(* Logix 5000 project; controller TritexII_Demo vendor 1 type 14 code 155 rev 32.11; software revision 32.02 *)

TASK MainTask (continuous, watchdog 500 ms) : MainProgram

MODULES
   Local : vendor 1 type 14 code 155 (PointIO 0, rev 32.11)
      Tritex : ETHERNET-MODULE (Ethernet 192.168.0.254, rev 1.1, Output RPI 80 ms)
           Tritex:C   // Tritex Module - Control
           Tritex:I   // Tritex Module - Input
           Tritex:O.Data[10]   // Control Host Acceleration (high)
           Tritex:O.Data[12]   // Control input Events Move Edge
           Tritex:O.Data[2]   // Control input Events Move level
           Tritex:O.Data[11]   // Control Host Current
           Tritex:O.Data[1]   // Control input events mode
           Tritex:O.Data[3]   // Control input Events Motion
           Tritex:O.Data[4]   // Control Host Command Mode
           Tritex:O.Data[5]   // Control Host Position (low)
           Tritex:O.Data[6]   // Control Host Position (high)
           Tritex:O.Data[7]   // Control Host Velocity (low)
           Tritex:O.Data[8]   // Control Host Velocity (high)
           Tritex:O.Data[9]   // Control Host Acceleration (low)
           Tritex:O   // Tritex Module - Output
      Discrete_IO : Embedded (PointIO 1, rev 32.11, Output RPI 20 ms)
           Local:1:C   // Module - Control
           Local:1:I.Data.1   // Enable Maintained
           Local:1:I.Data.2   // Home
           Local:1:I.Data.4   // Jog+
           Local:1:I.Data.5   // Jog-
           Local:1:I   // Module - Input
           Local:1:O   // Module - Output
END_MODULES

TYPE Exlar_Control :   // Tritex II Control
STRUCT
   EnableOutputs : INT;   // EnableOutputs
   InputEventsMode : INT;   // 4316
   InputEventsModeLevel : INT;   // 4318
   InputEventsMotion : INT;   // 4317
   HostCommandControlMode : INT;   // 4303
   HostPosition_low : INT;   // 4304
   HostPosition_high : INT;
   HostVelocity_low : INT;   // 4306
   HostVelocity_high : INT;
   HostAcceleration_low : INT;   // 4308
   HostAcceleration_high : INT;
   HostCurrent : INT;   // 4310
   InputEventsMoveEdge : INT;   // 4319
   JogSlowVelocity_low : INT;   // 6022
   JogSlowVelocity_high : INT;
   JogAcceleration_low : INT;   // 6026
   JogAcceleration_high : INT;
   MoveOption : INT;   // 6100
   MoveCurrentLimit : INT;   // 6101
   MoveAcceleration_low : INT;   // 6102
   MoveAcceleration_high : INT;
   MoveDeceleration_low : INT;   // 6500
   MoveDeceleration_high : INT;
   MovePrimaryOption : INT;   // 6106
   spare : INT;   // spare
   MovePrimaryPosition_low : INT;   // 6108
   MovePrimaryPosition_high : INT;
   MovePrimaryVelocity_low : INT;   // 6110
   MovePrimaryVelocity_high : INT;
   MoveSecondaryOption : INT;   // 6112
   spare2 : INT;   // spare
   MoveSecondaryPosition_low : INT;   // 6114
   MoveSecondaryPosition_high : INT;
   MoveSecondaryVelocity_low : INT;   // 6116
   MoveSecondaryVelocity_high : INT;
END_STRUCT
END_TYPE

TYPE Exlar_Drive :   // Tritex II Data
STRUCT
   Control : Exlar_Control;   // Control bits to send to the drive
   Status : Exlar_Status;   // Status bits received from the drive
END_STRUCT
END_TYPE

TYPE Exlar_Status :   // Tritex II Status
STRUCT
   EIP_Comm : INT;   // EIP module communication
   OutputEventsStatus : INT;   // 104
   OutputEventsMoveInPosition : INT;   // 108
   OutputEventsMotion : INT;   // 105
   OutputsEventsMotionActive : INT;   // 107
   PositionFeedback_low : INT;   // 378
   PositionFeedback_high : INT;
   SoftFaults : INT;   // 7
   HardFaults : INT;   // 6
   VelocityDisplay_low : INT;   // 356
   VelocityDisplay_high : INT;
   CurrentDisplay : INT;   // 567
   CurrentContinuous : INT;   // 565
   CurrentLimit : INT;   // 5108
   VoltageHallBattery : INT;   // 8
   VoltageBus : INT;   // 571
   TemperatureBoard : INT;   // 11
   TemperatureActuator : INT;   // 15
END_STRUCT
END_TYPE

ADD_ON_INSTRUCTION T2CON   (* revision 1.0, vendor Exlar Corporation *)
// Help:
// Use the Tritex 2 Control (T2CON) instruction to send commands to drive.
// Module commands includes enabling the drive, defining Home and Motion commands like Stop and Pause.
// Configured for Exlar EIP AOI. 07/01/2014
// ----------------------------------------------------------------------------------------------------------------------------
// Parameters Bit Definition
// ----------------------------------------------------------------------------------------------------------------------------
// Module:  (Input) Tritex 2 Module Commands
// ------------------------------------------------------------------
//      Module.0:     Enable Momentary
//      Module.1:     Enable Maintained
//      Module.2:     Define Home
//      Module.3:     Brake Override
//      Module.4:     Fault Reset
// Motion:  (Input) Tritex 2 Motion Commands
// ------------------------------------------------------------------
//      Motion.0:     Stop Motion
//      Motion.1:     Pause Move
//      Motion.2:     Initiate Home Move
//      Motion.3:     Emergency Move
VAR_IN_OUT
   Drive : Exlar_Drive; {required}   // Drive
END_VAR
VAR_INPUT
   Module : INT; {visible}   // Module Commands
        .0   // Enable Momentary
        .3   // Brake Override
        .1   // Enable Maintained
        .2   // Define Home
        .4   // Fault Reset
   Motion : INT; {visible}   // Motion Commands
        .2   // Initiate Home Move
        .1   // Pause Move
        .3   // Emergency Move
        .0   // Stop Motion
END_VAR
VAR_OUTPUT
   DF : BOOL; {access Read Only, visible}   // Indicates one or more Drive Faults are Active
END_VAR

ROUTINE Logic   (* structured text *)
   (***********************************************)
   (*   Exlar Tritex 2 Control                    *)
   (*                                             *)
   (***********************************************)
   
   (********** Inputs ***********)
   
   (* Module Register *)
   	(* 4316.0 Enable Momentary *)
   	if Module.0	then
   		Drive.Control.InputEventsMode.0	:= 1;
   	else
   		Drive.Control.InputEventsMode.0 := 0;
   	end_if;
   
   	(* 4316.1 Enable Maintained *)
   	if Module.1	then
   		Drive.Control.InputEventsMode.1	:= 1;
   	else
   		Drive.Control.InputEventsMode.1	 := 0;
   	end_if;
   
   	(* 4316.10 Define Home *)
   	if Module.2	then
   		Drive.Control.InputEventsMode.10 := 1;
   	else
   		Drive.Control.InputEventsMode.10 := 0;
   	end_if;
   
   	(* 4316.14 Brake Override *)
   	if Module.3	then
   		Drive.Control.InputEventsMode.14 := 1;
   	else
   		Drive.Control.InputEventsMode.14 := 0;
   	end_if;
   
   	(* 4316.15 Fault Reset *)
   	if Module.4	then
   		Drive.Control.InputEventsMode.15 := 1;
   	else
   		Drive.Control.InputEventsMode.15 := 0;
   	end_if;
   
   (* Motion Register *)
   	(* 4317.2 Stop Motion *)
   	if Motion.0	then
   		Drive.Control.InputEventsMotion.2 := 1;
   	else
   		Drive.Control.InputEventsMotion.2  := 0;
   	end_if;
   
   	(* 4317.3 Pause Move *)
   	if Motion.1	then
   		Drive.Control.InputEventsMotion.3 := 1;
   	else
   		Drive.Control.InputEventsMotion.3 := 0;
   	end_if;
   
   	(* 4317.8 Initiate Home Move *)
   	if Motion.2	then
   		Drive.Control.InputEventsMotion.8:= 1;
   	else
   		Drive.Control.InputEventsMotion.8 := 0;
   	end_if;
   
   	(* 4317.10 Dedicated Position EMove *)
   	if Motion.3	then
   		Drive.Control.InputEventsMotion.10 := 1;
   	else
   		Drive.Control.InputEventsMotion.10  := 0;
   	end_if;
   
   (*********** OUTPUTS  ***********)
   
   (* Drive Faults Active *)
   	If Drive.Control.InputEventsMode.3 then
    		DF := 1;
   	Else
   		DF := 0;
   	End_If;
   
END_ROUTINE
END_ADD_ON_INSTRUCTION

ADD_ON_INSTRUCTION T2DRIVE   (* revision 1.0 *)
// Drive Communication
VAR_IN_OUT
   Drive_Input : INT[101]; {required}
   Drive_Output : INT[101]; {required}
   Drive : Exlar_Drive; {required}
END_VAR
VAR_OUTPUT
   ER : BOOL; {access Read Only, visible}   // Fault
   Status : DINT; {access Read Only, visible}   // EIP interface Status
END_VAR
VAR_INPUT
   OutputEnable : BOOL; {access Read Only, visible}
END_VAR

ROUTINE Logic   (* structured text *)
   (***********************************************)
   (*   Exlar Tritex 2 Drive                      *)
   (*                                             *)
   (***********************************************)
   
   	(* Enable EtherNet/IP communication board *)
   	if OutputEnable then
   		Drive.Control.EnableOutputs.0 := 1;
   	else
   		Drive.Control.EnableOutputs.0 := 0;
   	end_if;
   
   
   	(* Note: If Tritex II translation tables length are changed,
   	   CPS data size and data Type needs to change *)
   
   	(* Copy Implicit Input data to PLC Internal register - Default 18 words*)
   	cps(Drive_Input[0],Drive.Status,18);
   
   
   	(* Copy Internal registers to PLC Implicit Output - Default 36 words *)
   	cps(Drive.Control, Drive_Output[0],36);
   
   
   	(* Tritex communication status *)
   	if 	Drive.Status.EIP_Comm.0 or
   		Drive.Status.EIP_Comm.1 or
   		Drive.Status.EIP_Comm.2 then
   		ER := 1;
   	else
   		ER := 0;
   	end_if;
   
   
   	(* Copy  Communication Status registers *)
   		Status := Drive.Status.EIP_Comm;
   		Status := Status AND 16#0000FFFF;
   
   	 (* StatusRegister
   		  	Bit				Description
   			=======			===============================
   			.0				Error - Tritex responded with error code
   							Read Extended Module Status(Object 64h,Instance 1,Attribute 101) for Modbus error
   			.1				Error - Communication between EIP module and Tritex timed-out
   			.2				Error - Communication between EIP module and Tritex cannot be established
   			.3-7			Reserved
   			.8				EIP interface is currently active at factory defaults
   			.9				EIP interface has a new configuration
   			.10-15			Reserved
   	 *)
END_ROUTINE
END_ADD_ON_INSTRUCTION

ADD_ON_INSTRUCTION T2HC   (* revision 1.1, vendor Exlar Corporation *)
// Help:
// Use the Tritex 2 HC(T2HC) instruction to control drive Host Control Option
// Configured for Exlar EIP AOI. 07/01/2014
// ----------------------------------------------------------------------------------------------------------------------------
// Parameters Bit Definition
// ----------------------------------------------------------------------------------------------------------------------------
// CommandMode:   (Input) Control Host Mode
// ------------------------------------------------------------------
//    0 = Disable Host Control
//    5 = Position
//    6 = Velocity
//    7 = Current
VAR_IN_OUT
   Drive : Exlar_Drive; {required}   // Drive
   Units : REAL[5]; {required}   // Units
END_VAR
VAR_INPUT
   CommandMode : INT; {visible}   // Host Control
   Position : REAL; {visible}   // Position
   Velocity : REAL; {visible}   // Velocity
   Acceleration : INT; {visible}   // Acceleration
   Current : REAL; {visible}   // Current
END_VAR
VAR_OUTPUT
   DF : BOOL; {access Read Only, visible}   // A Drive Fault is active
   ER : BOOL; {access Read Only, visible}   // A Instruction error is Active
END_VAR
VAR
   tempDINT : DINT; {access None}   // Temporary Register used in calculating units
END_VAR

ROUTINE Logic   (* structured text *)
   (***********************************************)
   (*   Exlar Tritex 2 Host Control               *)
   (*                                             *)
   (***********************************************)
   
   
   (* Precondition  *)
   	ER	:= 0;
   
   (* Check valid Host Control *)
   	(* CommandMode
   		 0 = Disabled
            5 = Position
            6 = Velocity
            7 = Current
   	*)
   	if CommandMode = 0 OR CommandMode = 5
   		OR CommandMode = 6 OR CommandMode = 7 then
   
   		(* ID:4303, Control.Host.CommandMode:  Outputs[4]] *)
   		Drive.Control.HostCommandControlMode := CommandMode;
   	else
   		ER	:= 1;
   		Drive.Control.HostCommandControlMode := 0;
   	end_if;
   
   
   (********** Outputs **********)
   (* Drive Faults Active *)
   	(* 104.03 Fault *)
   	if Drive.Status.OutputEventsStatus.3 then
    		DF := 1;
   	Else
   		DF := 0;
   	End_If;
   
   
   (* Error Test *)
   	(* User Units Instruction error active ? *)
   	IF Units[0] = 0 THEN
   		ER	:= 1;
   	end_if;
   
   (* Update Units *)
   	if NOT ER  then
   
   		(* Position *)
   		(* ID:4304, Control.Host.Postion:  ModuleOutputs[6],ModuleOutputs[5] *)
   		tempDINT := Position / Units[1];
   		cps(tempDINT, Drive.Control.HostPosition_low,2);
   
   		(* Velocity *)
   		(* ID:4306, Control.Host.Velocity:  ModuleOutputs[8],ModuleOutputs[7] *)
   		tempDINT := Velocity / Units[2];
   		cps(tempDINT, Drive.Control.HostVelocity_low,2);
   
   		(* Acceleration *)
   		(* ID:4308, Control.Host.Acceleration:  ModuleOutputs[10],ModuleOutputs[9] *)
   		tempDINT := Acceleration / Units[3];
   		cps(tempDINT, Drive.Control.HostAcceleration_low,2);
   
   		(* Current Scale   *)
   		(*       0: AMPs   *)
   		(*       1: %      *)
   		(* ID:4310, Control.Host.Current:  ModuleOutputs[11] *)
   		if Units[4] = 0	then
   			Drive.Control.HostCurrent := Current / 0.0078125 ;
   		else
   			(* Use for % ,ID:5108, Config.CurrentLimit:   ModuleInputs[13],  *)
   			Drive.Control.HostCurrent := Drive.Status.CurrentLimit * (Current /100);
   		end_if;
   
   	end_if;
   
   
   
END_ROUTINE
END_ADD_ON_INSTRUCTION

ADD_ON_INSTRUCTION T2JOG   (* revision 1.1, vendor Exlar Corporation *)
// Help:
// Use the Tritex 2 Jog (T2JOG) instruction to move an a drive at a constant speed until you tell it to stop.
// Jog commands includes enabling Jog Positive or Negative.  The instruction allow user to select profile velocity and acceleration in user units.
// Configured for Exlar EIP AOI. 07/01/2014
// ----------------------------------------------------------------------------------------------------------------------------
// Parameters Bit Definition
// ----------------------------------------------------------------------------------------------------------------------------
// Direction:  (Input) Command Jog Direction
// ------------------------------------------------------------------
//      Direction.0:     Jog Plus
//      Direction.1:     Jog Minus
// Active:  (Output) Jog status information
// ------------------------------------------------------------------
//      Active.0:     Jog Plus active
//      Active.1:     Jog Minus active
//      Active.2:     Ready
VAR_IN_OUT
   Drive : Exlar_Drive; {required}   // Drive
   Units : REAL[5]; {required}   // User Units Configuration
END_VAR
VAR_INPUT
   Direction : INT; {access Read Only, visible}   // Jog Control
        .0   // JOGP
        .1   // JOGN
   Velocity : REAL; {access Read Only, visible}   // Speed to move the drive in Speed Units.
   Acceleration : REAL; {access Read Only, visible}   // Acceleration rate of the drive in Accel Units.
END_VAR
VAR_OUTPUT
   DF : BOOL; {access Read Only, visible}   // A Drive Fault is active
   ER : BOOL; {access Read Only, visible}   // A Instruction error is Active
   Active : INT; {access Read Only, visible}   // Jog Active States
        .0   // JOGP
        .3   // READY
        .1   // JOGN
        .2   // STOPPED
END_VAR
VAR
   tempDINT : DINT; {access None}   // Temporary Register used in calculating units
END_VAR

ROUTINE Logic   (* structured text *)
   (***********************************************)
   (*   Exlar Tritex 2 Jog                        *)
   (*                                             *)
   (***********************************************)
   
   
   
   (*********** INPUTS ***********)
   
   (* Direction *)
   	(* 4317.4 Jog Positive *)
   	If Direction.0 Then
   		Drive.Control.InputEventsMotion.4 := 1;
   	else
   		Drive.Control.InputEventsMotion.4 := 0;
   	end_if;
   
   	(* 4317.5 Jog Minus *)
   	If Direction.1 Then
   		Drive.Control.InputEventsMotion.5 := 1;
   	else
   		Drive.Control.InputEventsMotion.5 := 0;
   	end_if;
   
   (*********** OUTPUTS  ***********)
   
   (* Drive Faults Active *)
   	(* 104.03 Fault *)
   	If Drive.Status.OutputEventsStatus.3 then
    		DF := 1;
   	Else
   		DF := 0;
   	End_If;
   
   (* Active States  *)
   	(* 105.3 JOG Positive *)
   	If Drive.Status.OutputEventsMotion.3 Then
   		Active.0 := 1;
   	else
   		Active.0 := 0;
   	end_if;
   
   	(* 105.4 JOG Minus *)
   	If Drive.Status.OutputEventsMotion.4 Then
   		Active.1 := 1;
   	else
   		Active.1 := 0;
   	end_if;
   
   
   	(* 105.0 STOPPED *)
   	If Drive.Status.OutputEventsMotion.0 Then
   		Active.2 := 1;
   	else
   		Active.2 := 0;
   	end_if;
   
   	(* 104.2 Ready *)
   	If Drive.Status.OutputEventsStatus.2 Then
   		Active.3 := 1;
   	else
   		Active.3 := 0;
   	end_if;
   
   
   (* Convert Units *)
   	IF Units[0] = 0 THEN
   		ER	:= 1;
   	else
   		ER  := 0;
   
   		(* Jog.SlowVelovity : ModuleOutputs[14],ModuleOutputs[13] *)
   		tempDINT := Velocity / Units[2];
   		cps(tempDINT, Drive.Control.JogSlowVelocity_low,2);
   
   		(* Jog.Acceleration: ModuleOutputs[16],ModuleOutputs[15] *)
   		tempDINT := Acceleration / Units[3];
   		cps(tempDINT, Drive.Control.JogAcceleration_low,2);
   
   	end_if;
END_ROUTINE
END_ADD_ON_INSTRUCTION

ADD_ON_INSTRUCTION T2MOV   (* revision 1.1, vendor Exlar Corporation *)
// Help:
// Use the Tritex 2 Move (T2MOV) instruction to execute an drive move command
// The Move instruction is used to set up move profile parameters for both primary and secondary move.  The AOI also includes the ability to control the execution of the move.
// Configured for Exlar EIP AOI. 07/01/2014
// ----------------------------------------------------------------------------------------------------------------------------
// Parameters Bit Definition
// ----------------------------------------------------------------------------------------------------------------------------
// Execute:   (Input) Control Move 0 commands
// ------------------------------------------------------------------
//      Execute.0:     Move 0 Maintained
//      Execute.1:     Move 0 Momentary
// Options:   (Input) Move 0 Options
// ------------------------------------------------------------------
//      Options.0:     Secondary Motion Enable
// PrimOption:   (Input) Move 0 Primary Options
// ------------------------------------------------------------------
//      PrimOption.2.1.0:    Three bits determine Primary Move Options
//                                     %000 = Absolute Position
//                                     %001 = Incremental
//                                     %010 = Unlimited(+)
//                                     %011 = Unlimted(-)
//                                     %100 = Absolute(+) only
//                                     %101 = Absolute(-) only
//      PrimOption.3:     Limit maximum Current
//      PrimOption.4:     Terminate on Current Limit
//      PrimOption.5:     Fault if terminated by current limit
// SecOption:   (Input) Move 0 Secondary Options
// ------------------------------------------------------------------
//      SecOption.2.1.0:    Three bits determine Secondary Move Options
//                                     %000 = Absolute Position
//                                     %001 = Incremental
//                                     %010 = Unlimited(+)
//                                     %011 = Unlimted(-)
//                                     %100 = Absolute(+) only
//                                     %101 = Absolute(-) only
//      SecOption.3:     Limit maximum Current
//      SecOption.4:     Terminate on Current Limit
//      SecOption.5:     Fault if terminated by current limit
// Active:  (Output) Move 0 status information
// ------------------------------------------------------------------
//      Active.0:     Ready -  is set when both the ENABLED and HOMED flags are active.
//      Active.1:     Move 0 in Position
//      Active.2:     Move 0 active
VAR_IN_OUT
   Drive : Exlar_Drive; {required}   // Drive
   Units : REAL[5]; {required}   // Units
END_VAR
VAR_INPUT
   Execute : INT; {visible}   // Move Control
        .1   // Momentary
        .0   // Maintained
   Options : INT; {visible}   // Move Options
        .0   // Secondary Motion Enable
   CurrentLimit : REAL; {visible}   // Move Current Limit
   Acceleration : INT; {visible}   // Acceleration rate of the drive in Accel Units
   Deceleration : INT; {visible}   // Deceleration rate of the drive in Accel Units
   Prim_Position : REAL; {visible}   // Absolute position or incremental distance for the move
   Prim_Velocity : REAL; {visible}   // Speed to move the drive in Speed Units
   Prim_Option : INT; {visible}   // Primary Move Options
        .3   // Limit maximum Current
        .4   // Terminate on Current Limit
        .5   // Fault if terminated by current limit
        .0   // TYPE Bit
        .1   // TYPE Bit
        .2   // TYPE Bit
   Sec_Position : REAL; {visible}   // Absolute position or incremental distance for the move
   Sec_Velocity : REAL; {visible}   // Speed to move the drive in Speed Units
   Sec_Option : INT; {visible}   // Secondary Move Options
        .3   // Limit maximum Current
        .4   // Terminate on Current Limit
        .5   // Fault if terminated by current limit
        .0   // TYPE Bit
        .1   // TYPE Bit
        .2   // TYPE Bit
END_VAR
VAR_OUTPUT
   DF : BOOL; {access Read Only, visible}   // A Drive Fault is active
   ER : BOOL; {access Read Only, visible}   // A Instruction error is Active
   IP : BOOL; {access Read Only, visible}   // Move 0 In Position
   Active : INT; {access Read Only, visible}   // Active
        .1   // Move 0 In Position
        .2   // Move 0 active
        .0   // Ready
END_VAR
VAR
   tempDINT : DINT; {access None}   // Temporary Register used in calculating units
END_VAR

ROUTINE Logic   (* structured text *)
   (***********************************************)
   (*   Exlar Tritex 2 Move                       *)
   (*                                             *)
   (***********************************************)
   (*
    Revision History
    -------
    3.7.2023   Fixed bug of array pointer for Modbus ID 6101 scaling
   
   *)
   
   (********** Inputs ***********)
   
   (* Execute *)
   	(* 4318.0  Move 0 Maintained *)
   	if Execute.0 then
   		Drive.Control.InputEventsModeLevel.0 := 1;
   	else
   		Drive.Control.InputEventsModeLevel.0 := 0;
   	end_if;
   
   	(* 4319.0  Move 0 Momentary *)
   	if Execute.1 then
   		Drive.Control.InputEventsMoveEdge.0 := 1;
   	else
   		Drive.Control.InputEventsMoveEdge.0 := 0;
   	end_if;
   
   (* Option *)
   	(* 6100.0  Secondary Motion Enable *)
   	if Options.0 then
   		Drive.Control.MoveOption.0 := 1;
   	else
   		Drive.Control.MoveOption.0 := 0;
   	end_if;
   
   (* Primary Option *)
   	(* 6106.0  - Move Type *)
   	if Prim_Option.0 then
   		Drive.Control.MovePrimaryOption.0 := 1;
   	else
   		Drive.Control.MovePrimaryOption.0 := 0;
   	end_if;
   	(* 6106.1  - Move Type *)
   	if Prim_Option.1 then
   		Drive.Control.MovePrimaryOption.1 := 1;
   	else
   		Drive.Control.MovePrimaryOption.1 := 0;
   	end_if;
   	(* 6106.2  - Move Type *)
   	if Prim_Option.2 then
   		Drive.Control.MovePrimaryOption.2 := 1;
   	else
   		Drive.Control.MovePrimaryOption.2 := 0;
   	end_if;
   
   	(* 6106.4 Limit maximum Current *)
   	if Prim_Option.3 then
   		Drive.Control.MovePrimaryOption.4 := 1;
   	else
   		Drive.Control.MovePrimaryOption.4 := 0;
   	end_if;
   
   	(* 6106.8 Terminate on Current Limit *)
   	if Prim_Option.4 then
   		Drive.Control.MovePrimaryOption.8 := 1;
   	else
   		Drive.Control.MovePrimaryOption.8 := 0;
   	end_if;
   
   	(* 6106.12 Fault if terminated by current limit *)
   	if Prim_Option.5 then
   		Drive.Control.MovePrimaryOption.12 := 1;
   	else
   		Drive.Control.MovePrimaryOption.12 := 0;
   	end_if;
   
   (* Secondary Option	*)
   	(* 6112.0  - Move Type *)
   	if Sec_Option.0 then
   		Drive.Control.MoveSecondaryOption.0:= 1;
   	else
   		Drive.Control.MoveSecondaryOption.0	:= 0;
   	end_if;
   
   	(* 6112.1  - Move Type *)
   	if Sec_Option.1 then
   		Drive.Control.MoveSecondaryOption.1	 := 1;
   	else
   		Drive.Control.MoveSecondaryOption.1	 := 0;
   	end_if;
   
   	(* 6112.2  - Move Type *)
   	if Sec_Option.2 then
   		Drive.Control.MoveSecondaryOption.2	 := 1;
   	else
   		Drive.Control.MoveSecondaryOption.2	 := 0;
   	end_if;
   
   	(* 6112.4 Limit maximum Current *)
   	if Sec_Option.3 then
   		Drive.Control.MoveSecondaryOption.4	 := 1;
   	else
   		Drive.Control.MoveSecondaryOption.4	 := 0;
   	end_if;
   
   	(* 6112.8 Terminate on Current Limit *)
   	if Sec_Option.4 then
   		Drive.Control.MoveSecondaryOption.8	 := 1;
   	else
   		Drive.Control.MoveSecondaryOption.8	 := 0;
   	end_if;
   
   	(* 6112.12 Fault if terminated by current limit *)
   	if Sec_Option.5 then
   		Drive.Control.MoveSecondaryOption.12	 := 1;
   	else
   		Drive.Control.MoveSecondaryOption.12	 := 0;
   	end_if;
   
   
   (********** Outputs **********)
   (* Drive Faults Active *)
   	(* 104.03 Fault *)
   	If Drive.Status.OutputEventsStatus.3 then
    		DF := 1;
   	Else
   		DF := 0;
   	End_If;
   
   (* Active *)
   	(* 104.2 Ready *)
   	If Drive.Status.OutputEventsStatus.2 Then
   		Active.0 := 1;
   	else
   		Active.0 := 0;
   	end_if;
   
   	(* 108.0 Move 0 in Position *)
   	If Drive.Status.OutputEventsMoveInPosition.0 Then
   		Active.1 := 1;
   		IP := 1;
   	else
   		Active.1 := 0;
   		IP := 0;
   	end_if;
   
   	(* 107.0 Move 0 Moving *)
   	If Drive.Status.OutputsEventsMotionActive.0 Then
   		Active.2 := 1;
   	else
   		Active.2 := 0;
   	end_if;
   
   
   (* Convert Units *)
   	IF Units[0] = 0 THEN
   		ER	:= 1;
   	else
   		ER  := 0;
   
   		(** Move Group **)
   	 	(* ID:6102, Move.0.Acceleration:  ModuleOutputs[20],ModuleOutputs[19] *)
   		tempDINT := Acceleration / Units[3];
   		cps(tempDINT, Drive.Control.MoveAcceleration_low,2);
   
   		(* ID:6500, Move.0.Deceleration:  ModuleOutputs[22],ModuleOutputs[21] *)
   		tempDINT := Deceleration / Units[3];
   		cps(tempDINT, Drive.Control.MoveDeceleration_low,2);
   
   		(* Primary Group **)
   		(* ID:6110, Move.0.Primary.Velocity:  ModuleOutputs[28],ModuleOutputs[27] *)
   		tempDINT := Prim_Velocity / Units[2];
   		cps(tempDINT, Drive.Control.MovePrimaryVelocity_low,2);
   
   		(* Secondary Group **)
   		(* ID:6116, Move.0.Secondary.Velocity:  ModuleOutputs[34],ModuleOutputs[33] *)
   		tempDINT := Sec_Velocity / Units[2];
   		cps(tempDINT, Drive.Control.MoveSecondaryVelocity_low,2);
   
   		(* ID:6114, Move.0.Secondary.Position:  ModuleOutputs[32],ModuleOutputs[31] *)
   		tempDINT := Sec_Position / Units[1];
   		cps(tempDINT, Drive.Control.MoveSecondaryPosition_low,2);
   
   		(* ID:6108, Move.0.Primary.Position:  ModuleOutputs[26],ModuleOutputs[25] *)
   		tempDINT := Prim_Position / Units[1];
   		cps(tempDINT, Drive.Control.MovePrimaryPosition_low,2);
   
   
   		(* Current Scale   *)
   		(*       0: AMPs   *)
   		(*       1: %      *)
   		(* ID:6101,  Move.0.CurrentLimit:  ModuleOutputs[18] *)
   		if Units[4] = 0	then
   			Drive.Control.MoveCurrentLimit := CurrentLimit / 0.0078125 ;
   		else
   			(* Use for % ,ID:5108, Config.CurrentLimit:   ModuleInputs[13],  *)
   			Drive.Control.MoveCurrentLimit := Drive.Status.CurrentLimit * (CurrentLimit /100);
   		end_if;
   	end_if;
   
   
   
   
   
   
   
   
   
   
END_ROUTINE
END_ADD_ON_INSTRUCTION

ADD_ON_INSTRUCTION T2STA   (* revision 1.0, vendor Exlar Corporation *)
// Help:
// Use the Tritex 2 Status (T2STA) instruction to retrieve drive status. The instruction parameters provide a summary view of the module, motion and position information for the drive.
// Configured for Exlar EIP AOI. 07/01/2014
// ----------------------------------------------------------------------------------------------------------------------------
// Parameters Bit Definition
// ----------------------------------------------------------------------------------------------------------------------------
// Module:   (Output) Module Status
// ------------------------------------------------------------------
//      Module.0:     Enable
//      Module.1:     Homed
//      Module.2:     Ready
//      Module.3:     Fault Active
//      Module.4:     Warning Active
//      Module.5:     Fault or Warning Active
// Motion:   (Output) Motion Status
// ------------------------------------------------------------------
//      Motion.0:     Stopped Active
//      Motion.1:     Pasued Active
//      Motion.2:     Jogged Active
//      Motion.3:     Jog Positive Active
//      Motion.4:     Jog Negative Active
//      Motion.5:     Initiate Home Move Active
//      Motion.6:     Emergency Move Active
//      Motion.7:     Move Active
//      Motion.8:     In Position Active
// Warnings:     (Output) List of active drive Warnings
// ------------------------------------------------------------------
//      Warnings.0:  IPK – Peak Current
//      Warnings.1:  C – Continuous Current
//      Warnings.2:  POS – Position Tracking
//      Warnings.3:  MV – Move Termination
//      Warnings.4:  VLOW – Low DC Bus Voltage
//      Warnings.5:  VHIGH – High DC Bus Voltage
//      Warnings.6:  FE – Positional Following Error
//      Warnings.7:  BT – Board Temperature
//      Warnings.8:  AT – Actuator Temperature
//      Warnings.9:  LOS – Loss of Signal
//      Warnings.10:  COM –Communications
//      Warnings.11:  IH – Hardware Over current
//      Warnings.12:  HB – Absolute Hall Board Battery
//      Warnings 13:  UP – User Parameters
//      Warnings.14:  FP – Factory Parameters
//      Warnings.15:  RS – Restart
// Faults:     (Output)  List of active drive Faults
// ------------------------------------------------------------------
//      Faults.0:  IPK – Peak Current
//      Faults.1:  C – Continuous Current
//      Faults.2:  POS – Position Tracking
//      Faults.3:  MV – Move Termination
//      Faults.4:  VLOW – Low DC Bus Voltage
//      Faults.5:  VHIGH – High DC Bus Voltage
//      Faults.6:  FE – Positional Following Error
//      Faults.7:  BT – Board Temperature
//      Faults.8:  AT – Actuator Temperature
//      Faults.9:  LOS – Loss of Signal
//      Faults.10:  COM –Communications
//      Faults.11:  IH – Hardware Over current
//      Faults.12:  HB – Absolute Hall Board Battery
//      Faults 13:  UP – User Parameters
//      Faults.14:  FP – Factory Parameters
//      Faults.15:  RS – Restart
VAR_IN_OUT
   Drive : Exlar_Drive; {required}   // Drive
   Units : REAL[5]; {required}   // User Units Configuration
END_VAR
VAR_OUTPUT
   DF : BOOL; {access Read Only, visible}   // A Drive Fault is active
   ER : BOOL; {access Read Only, visible}   // A Instruction error is Active
   Ready : BOOL; {access Read Only, visible}   // Enabled + Homed
   Module : INT; {access Read Only, visible}   // Drive Status
        .10   // Define Home Position 1
        .11   // Define Home Position 2
        .7   // Alternate Operating Mode
        .13   // Teach Selected Move Position
        .15   // Fault Reset
        .1   // Homed
        .2   // Ready
        .12   // Move Teach Enable
        .0   // Enable
        .3   // Fault
        .4   // Warning
        .14   // Brake Override
        .5   // Fault or Warning
   Motion : INT; {access Read Only, visible}   // Motion Status
        .8   // In Position active
        .6   // EMOVE
        .3   // Jog Positive Actived
        .1   // Pasued Active
        .2   // Jogged Active
        .0   // Stopped Active
        .5   // Initiate Home Move Active
        .4   // Jog Negative Active
        .7   // Move active
   Position : REAL; {access Read Only, visible}   // Module Position
   Velocity : REAL; {access Read Only, visible}   // Module Velocity
   ContinuousCurrent : REAL; {access Read Only, visible}   // Continous Current
   ActualCurrent : REAL; {access Read Only, visible}   // Actual Current
   Battery : INT; {access Read Only, visible}   // Battery Voltage if available
   BusVoltage : INT; {access Read Only, visible}   // Bus Voltage
   BoardTemp : INT; {access Read Only, visible}   // Board Temperature
   ActuatorTemp : INT; {access Read Only, visible}   // Actuator Temperature
   Warnings : INT; {access Read Only, visible}   // Warnings
        .12   // AB- Absolute Hall Board Battery
        .1   // C - Continuous Current
        .10   // COM - Communications
        .11   // IH - Hardware Over current
        .0   // IPK- Peak Current
        .13   // UP - User Parameters
        .3   // MV - Move Termination
        .5   // VHIGH - High DC Bus Voltage
        .6   // FE - Positional Following Error
        .7   // BT - Board Temperature
        .14   // FP - Factory Parameters
        .9   // LOS - Loss of Signal
        .4   // VLOW - Low DC Bus Voltage
        .15   // RS - Restart
        .2   // POS - Position Tracking
        .8   // AT - Actuator Temperature
   Faults : INT; {access Read Only, visible}   // Faults
        .0   // IPK- Peak Current
        .1   // C - Continuous Current
        .10   // COM - Communications
        .11   // IH - Hardware Over current
        .12   // HB - Absolute Hall Board Battery
        .13   // UP - User Parameters
        .3   // MV - Move Termination
        .5   // VHIGH - High DC Bus Voltage
        .6   // FE - Positional Following Error
        .7   // BT - Board Temperature
        .14   // FP - Factory Parameters
        .9   // LOS - Loss of Signal
        .4   // VLOW - Low DC Bus Voltage
        .2   // POS - Position Tracking
        .15   // RS - Restart
        .8   // AT - Actuator Temperature
END_VAR
VAR
   tempDINT : DINT; {access None}   // Temporary Register used in calculating units
END_VAR

ROUTINE Logic   (* structured text *)
   (***********************************************)
   (*   Exlar Tritex 2 Status                     *)
   (*                                             *)
   (***********************************************)
   
   (*********** OUTPUTS  ***********)
   
   (* Drive Faults Active *)
   	(* 104.03 Fault *)
   	If Drive.Status.OutputEventsStatus.3 then
    		DF := 1;
   	Else
   		DF := 0;
   	End_If;
   
   (* Ready Active *)
   	(* 104.02 Ready *)
   	if Drive.Status.OutputEventsStatus.2 then
   		Ready := 1;
   	else
   		Ready := 0;
   	End_if;
   
   (* Drive Warnings Active *)
   (* ID:7, Status.Mode.SoftFaults : ModuleInputs[7]*)
   	Warnings := Drive.Status.SoftFaults;
   
   (* Drive Faults Active *)
   (* ID:6, Status.Mode.HardFaults : ModuleInputs[8]*)
   	Faults := Drive.Status.HardFaults;
   
   (* Module  *)
   	(* 104.00 Enable *)
   	(* 104.01 Homed *)
   	(* 104.02 Ready *)
   	(* 104.03 Fault *)
   	(* 104.04 Warning *)
   	(* 104.05 Fault or Warning *)
   	Module := Drive.Status.OutputEventsStatus AND 16#3F;
   
   (* Motion *)
   	(* 105.00 Stopped Active *)
   	If Drive.Status.OutputEventsMotion.0 Then
   		Motion.0 := 1;
   	else
   		Motion.0 := 0;
   	end_if;
   
   	(* 105.01 Pause *)
   	If Drive.Status.OutputEventsMotion.1 Then
   		Motion.1 := 1;
   	else
   		Motion.1 := 0;
   	end_if;
   
   	(* 105.02 Jogging *)
   	If Drive.Status.OutputEventsMotion.2 Then
   		Motion.2 := 1;
   	else
   		Motion.2 := 0;
   	end_if;
   
   	(* 105.03 Jogging Plus *)
   	If Drive.Status.OutputEventsMotion.3 Then
   		Motion.3 := 1;
   	else
   		Motion.3 := 0;
   	end_if;
   
   	(* 105.04 Jogging Minus *)
   	If Drive.Status.OutputEventsMotion.4 Then
   		Motion.4 := 1;
   	else
   		Motion.4 := 0;
   	end_if;
   
   	(* 105.05 Homing Active *)
   	If Drive.Status.OutputEventsMotion.5 Then
   		Motion.5 := 1;
   	else
   		Motion.5 := 0;
   	end_if;
   
   	(* 105.08 Dedicated Move Active *)
   	If Drive.Status.OutputEventsMotion.8 Then
   		Motion.6 := 1;
   	else
   		Motion.6 := 0;
   	end_if;
   
   	(* 105.09 Move Active *)
   	If Drive.Status.OutputEventsMotion.9 Then
   		Motion.7 := 1;
   	else
   		Motion.7 := 0;
   	end_if;
   
   	(* 105.12 Input Position *)
   	If Drive.Status.OutputEventsMotion.12 Then
   		Motion.8 := 1;
   	else
   		Motion.8 := 0;
   	end_if;
   
   (* Units  *)
   	IF Units[0] = 0 THEN
   		ER := 1;
   	else
   		ER := 0;
   
   		(* Velocity *)
   		(*  ID:356, Status.Velocity.Display:    ModuleInputs[10],ModuleInputs[9] *)
   		cps(Drive.Status.VelocityDisplay_low,tempDINT,2);
   		Velocity    :=  tempDINT * Units[2];
   
   		(* Position *)
   		(*	ID:378, Status.Position.Feedback:   ModuleInputs[6],ModuleInputs[5]  *)
   		cps(Drive.Status.PositionFeedback_low,tempDINT,2);
   		Position	:=	tempDINT * Units[1];
   
   		(* Current scale ? *)
   		(*       0: AMPs   *)
   		(*       1: %      *)
   		if Units[4] = 0	then
   			(* ID:567, Status.Current.Display:  ModuleInputs[11]  *)
   			ActualCurrent := Drive.Status.CurrentDisplay * 0.0078125;
   
   			(* ID:565, Status.Current.Continuous:  ModuleInputs[12]*)
   			ContinuousCurrent := Drive.Status.CurrentContinuous * 0.0078125;
   		else
   			(* Use for %,ID:5108, Config.CurrentLimit:   ModuleInputs[13],  *)
   			ActualCurrent  :=  (Drive.Status.CurrentDisplay / Drive.Status.CurrentLimit) * 100;
   			ContinuousCurrent :=  (Drive.Status.CurrentContinuous / Drive.Status.CurrentLimit) * 100;
   		end_if;
   	end_if;
   
   (*	ID:15,  Status.Temperature.Actuator:ModuleInputs[17] *)
    	ActuatorTemp 	:=	Drive.Status.TemperatureActuator * 0.125;
   (*	ID:11,  Status.Temperature.Board: 	ModuleInputs[16] *)
   	BoardTemp		:=	Drive.Status.TemperatureBoard * 0.03125;
   (*	ID:571, Status.Voltage.Vbus:    	ModuleInputs[15] *)
   	BusVoltage		:=	Drive.Status.VoltageBus *  0.03125;
   (*	ID:08,  Status.Voltage.HallBattery: ModuleInputs[14] *)
   
   
END_ROUTINE
END_ADD_ON_INSTRUCTION

ADD_ON_INSTRUCTION T2UU   (* revision 1.0, vendor Exlar Corporation *)
// Help:
// Use the Tritex 2 User Units (T2UU) instruction to calculate user units. User units are easy-to-understand units of measurement that simplify your programming tasks. You define user units via parameters DistUUPerRev, VelTimeScale and CurrentScale.
// Configured for Exlar EIP AOI. 07/01/2014
// ----------------------------------------------------------------------------------------------------------------------------
// Parameters Bit Definition
// ----------------------------------------------------------------------------------------------------------------------------
// VelTimeScale:  (Input) Select the units you want for velocity.
//                          This will also effect acceleration
// ------------------------------------------------------------------
//      VelTimeScale = 0:     Seconds  (Velocity: Units/S,  Acceleration:  Units/S/S)
//      VelTimeScale = 1:     Minutes    (Velocity: Units/M, Acceleration:  Units/S/M)
// CurrentScale:  (Input) Select the units you want for Current
// ------------------------------------------------------------------
//      CurrentScale = 0:     AMPS
//      CurrentScale = 1:     % of Current Limit (Modbus ID 5108)
VAR_INPUT
   DistScale : REAL; {visible}   // Distance User Units Per Rev
   VelScale : REAL; {visible}   // Velocity Scale
   AccScale : REAL; {visible}   // Acceleration Scale
   CurrentScaling : INT; {visible}   // Current Scale
END_VAR
VAR_IN_OUT
   Units : REAL[5]; {required}   // Units Scale Results
        [0]   // Status
        [2]   // Velocity Scale
        [3]   // Acceleration Scale
        [4]   // Current Scaling Method
        [1]   // Distance
END_VAR
VAR_OUTPUT
   ER : BOOL; {access Read Only, visible}   // A Instruction error is Active
END_VAR

ROUTINE Logic   (* structured text *)
   (***********************************************)
   (*   Exlar Tritex 2 User Units                 *)
   (*                                             *)
   (***********************************************)
   
   
   
   (* Check for Error *)
   	if ((DistScale = 0) or (VelScale = 0)or (AccScale = 0 ))then
   		ER := 1;
   		Units[0] := 0;
   	else
   		ER := 0;
   		Units[0] := 1;
   	End_if;
   
   (* Load Global Units       *)
   	(* Current Scale       *)
   	(*       0: AMPs       *)
   	(*       1: % of Rated *)
   
   	(* Distance User Units per Rev *)
   	(*Units[0] := Units Status *)
   	Units[1] := DistScale;
   	Units[2] := VelScale;
   	Units[3] := AccScale;
   	Units[4] := CurrentScaling AND 16#1;
   
   
   
END_ROUTINE
END_ADD_ON_INSTRUCTION

VAR_GLOBAL   (* controller tags *)
   CurrentFeedback : REAL := 0.0234375;   // Scale Current
   Drive_Control : T2CON;   // AOI - T2CON
   Drive_Host : T2HC := (Position := 20.0, Velocity := 500.0, Acceleration := 2000, Current := 5.0);   // AOI - T2HC
   Drive_Jog : T2JOG := (Velocity := 89.0, Acceleration := 40.0);   // AOI - T2JOG
   Drive_Move : T2MOV := (Options := 13, CurrentLimit := 45.0, Acceleration := 7, Deceleration := 7, Prim_Position := 2.0, Prim_Velocity := 5.0, Sec_Position := 4.542, Sec_Velocity := 1.5);   // AOI - T2MOV
   Drive_Status : T2STA := (Position := -1.5258789e-05, Velocity := 0.4899466, ContinuousCurrent := 0.0234375, ActualCurrent := 0.046875, BusVoltage := 24, BoardTemp := 43, ActuatorTemp := 24);   // AOI - T2STA
   Drive_Units : T2UU := (DistScale := 1.5258789e-05, VelScale := 3.5762787e-06, AccScale := 5.722046e-05);   // AOI - T2UU
   DriveCommunication : T2DRIVE := (OutputEnable := 1);
   Enabled : BOOL;   // Enabled command is Actived
   Fault_Reset : BOOL;   // Command Fault Reset
   Faulted : BOOL;   // Status indicate fault is active
   Home_input_switch : ALIAS FOR Local:1:I.Data.9;
   Home_Termination_Switch : ALIAS FOR Tritex:O.Data[35].0;
   Home_Tritex : BOOL;   // Use to execute the Absolute Home Command
   Homed : BOOL;   // Status indicates drive is homed
   Jogging_Minus : BOOL;   // Jog Neg Enable
   Jogging_Plus : BOOL;   // Joe Pos Enable
   Move_Active : BOOL;   // Status indicates Move Actived
   PostionFeedback : REAL := -0.00010681152;   // scale Position
   Ready : BOOL;   // Enabled and Homed actived
   VelocityFeedback : REAL := 0.08605242;   // Scale Velocity
END_VAR

PROGRAM MainProgram   (* main routine MainRoutine *)
VAR
   M0_InPos : BOOL;
   Move0 : BOOL;
   myUnits : REAL[5] := ([0] := 1.0, [1] := 1.5258789e-05, [2] := 3.5762787e-06, [3] := 5.722046e-05);
   TritexII_Drive : Exlar_Drive := (Control.EnableOutputs := 1, Control.HostPosition_high := 20, Control.HostVelocity_low := 21840, Control.HostVelocity_high := 2133, Control.HostAcceleration_low := 21844, Control.HostAcceleration_high := 533, Control.HostCurrent := 640, Control.JogSlowVelocity_low := -17476, Control.JogSlowVelocity_high := 379, Control.JogAcceleration_low := -21845, Control.JogAcceleration_high := 10, Control.MoveOption := 1, Control.MoveCurrentLimit := 346, Control.MoveAcceleration_low := -8738, Control.MoveAcceleration_high := 1, Control.MoveDeceleration_low := -8738, Control.MoveDeceleration_high := 1, Control.MovePrimaryPosition_high := 2, Control.MovePrimaryVelocity_low := 21845, Control.MovePrimaryVelocity_high := 21, Control.MoveSecondaryPosition_low := -30016, Control.MoveSecondaryPosition_high := 4, Control.MoveSecondaryVelocity_low := 26214, Control.MoveSecondaryVelocity_high := 6, Status.PositionFeedback_low := -1, Status.PositionFeedback_high := -1, Status.VelocityDisplay_low := 5927, Status.VelocityDisplay_high := 2, Status.CurrentDisplay := 6, Status.CurrentContinuous := 3, Status.CurrentLimit := 768, Status.VoltageBus := 753, Status.TemperatureBoard := 1379, Status.TemperatureActuator := 192);
END_VAR

ROUTINE BasicIndexing   (* ladder *)
// Example using AOI's
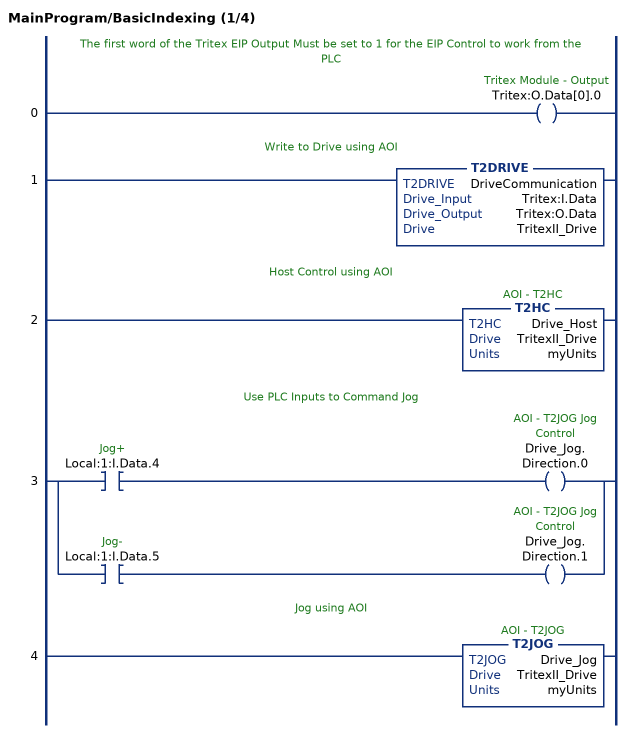
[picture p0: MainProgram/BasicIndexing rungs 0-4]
   // The first word of the Tritex EIP Output Must be set to 1 for the EIP Control to work from the PLC
   0: OTE(Tritex:O.Data[0].0);
   // Write to Drive using AOI
   1: T2DRIVE(DriveCommunication,Tritex:I.Data,Tritex:O.Data,TritexII_Drive);
   // Host Control using AOI
   2: T2HC(Drive_Host,TritexII_Drive,myUnits);
   // Use PLC Inputs to Command Jog
   3: [XIC(Local:1:I.Data.4) OTE(Drive_Jog.Direction.0) ,XIC(Local:1:I.Data.5) OTE(Drive_Jog.Direction.1) ];
   // Jog using AOI
   4: T2JOG(Drive_Jog,TritexII_Drive,myUnits);
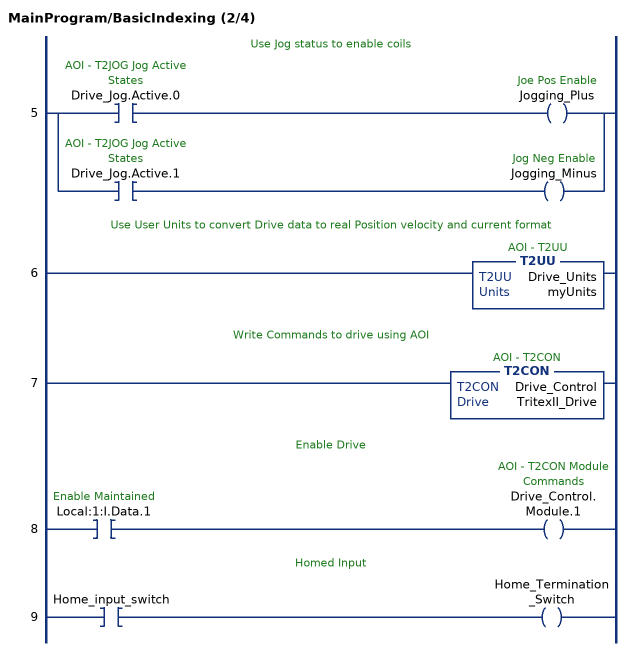
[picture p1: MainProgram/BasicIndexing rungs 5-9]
   // Use Jog status to enable coils
   5: [XIC(Drive_Jog.Active.0) OTE(Jogging_Plus) ,XIC(Drive_Jog.Active.1) OTE(Jogging_Minus) ];
   // Use User Units to convert Drive data to real Position velocity and current format
   6: T2UU(Drive_Units,myUnits);
   // Write Commands to drive using AOI
   7: T2CON(Drive_Control,TritexII_Drive);
   // Enable Drive
   8: XIC(Local:1:I.Data.1)OTE(Drive_Control.Module.1);
   // Homed Input
   9: XIC(Home_input_switch)OTE(Home_Termination_Switch);
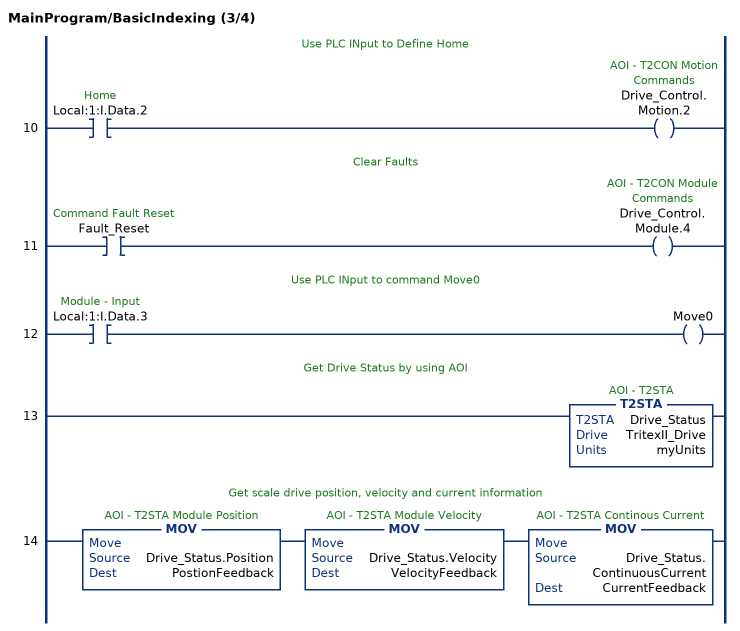
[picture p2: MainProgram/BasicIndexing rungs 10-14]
   // Use PLC INput to Define Home
   10: XIC(Local:1:I.Data.2)OTE(Drive_Control.Motion.2);
   // Clear Faults
   11: XIC(Fault_Reset)OTE(Drive_Control.Module.4);
   // Use PLC INput to command Move0
   12: XIC(Local:1:I.Data.3)OTE(Move0);
   // Get Drive Status by using AOI
   13: T2STA(Drive_Status,TritexII_Drive,myUnits);
   // Get scale drive position, velocity and current information
   14: MOV(Drive_Status.Position,PostionFeedback)MOV(Drive_Status.Velocity,VelocityFeedback)MOV(Drive_Status.ContinuousCurrent,CurrentFeedback);
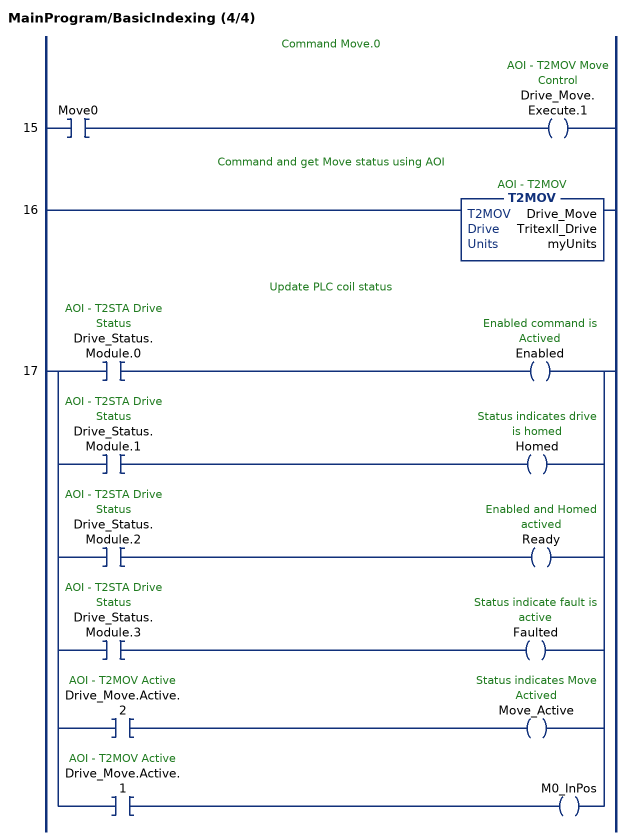
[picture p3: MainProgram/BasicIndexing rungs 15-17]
   // Command Move.0
   15: XIC(Move0)OTE(Drive_Move.Execute.1);
   // Command and get Move status using AOI
   16: T2MOV(Drive_Move,TritexII_Drive,myUnits);
   // Update PLC coil status
   17: [XIC(Drive_Status.Module.0) OTE(Enabled) ,XIC(Drive_Status.Module.1) OTE(Homed) ,XIC(Drive_Status.Module.2) OTE(Ready) ,XIC(Drive_Status.Module.3) OTE(Faulted) ,XIC(Drive_Move.Active.2) OTE(Move_Active) ,XIC(Drive_Move.Active.1) OTE(M0_InPos) ];
END_ROUTINE

ROUTINE Exlar_AOI_v2   (* ladder *)
// Routine contain all the available AOI for reference.
// This Routine is not Execute by the mainRoutine
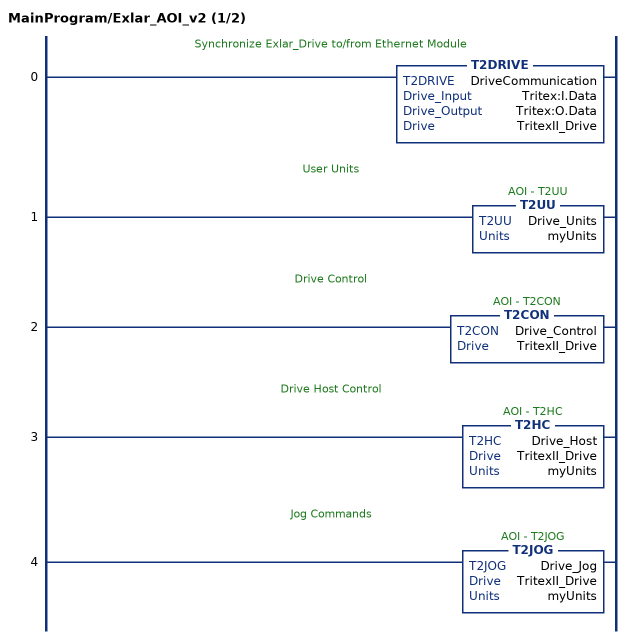
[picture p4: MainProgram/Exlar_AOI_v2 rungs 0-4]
   // Synchronize Exlar_Drive to/from Ethernet Module
   0: T2DRIVE(DriveCommunication,Tritex:I.Data,Tritex:O.Data,TritexII_Drive);
   // User Units
   1: T2UU(Drive_Units,myUnits);
   // Drive Control
   2: T2CON(Drive_Control,TritexII_Drive);
   // Drive Host Control
   3: T2HC(Drive_Host,TritexII_Drive,myUnits);
   // Jog Commands
   4: T2JOG(Drive_Jog,TritexII_Drive,myUnits);
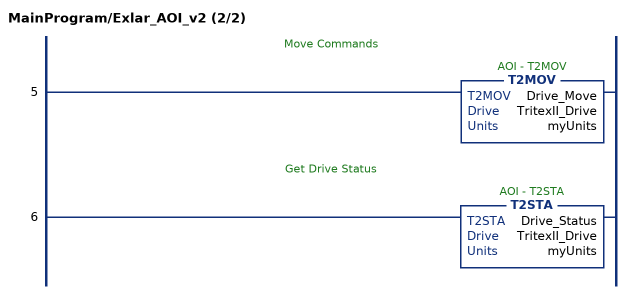
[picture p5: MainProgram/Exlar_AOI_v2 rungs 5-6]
   // Move Commands
   5: T2MOV(Drive_Move,TritexII_Drive,myUnits);
   // Get Drive Status
   6: T2STA(Drive_Status,TritexII_Drive,myUnits);
END_ROUTINE

ROUTINE MainRoutine   (* ladder *)
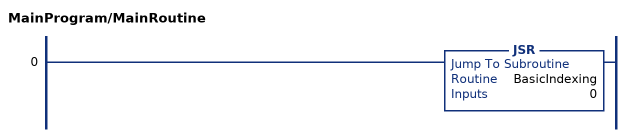
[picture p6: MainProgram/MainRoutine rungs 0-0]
   0: JSR(BasicIndexing,0);
END_ROUTINE
END_PROGRAM
